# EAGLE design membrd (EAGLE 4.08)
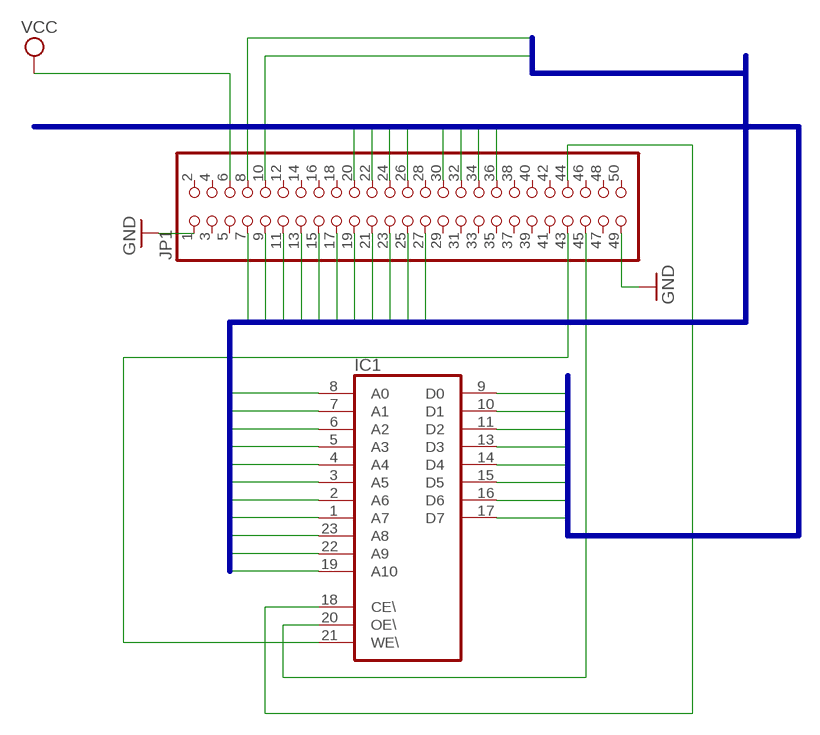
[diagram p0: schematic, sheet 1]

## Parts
IC1  2816  [DIL24]
JP1  PINHD-2X25  [2X25]

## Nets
A0: IC1.8(A0) JP1.27
A1: IC1.7(A1) JP1.25
A2: IC1.6(A2) JP1.23
A3: IC1.5(A3) JP1.21
A4: IC1.4(A4) JP1.19
A5: IC1.3(A5) JP1.17
A6: IC1.2(A6) JP1.15
A7: IC1.1(A7) JP1.13
A8: IC1.23(A8) JP1.11
A9: IC1.22(A9) JP1.9
A10: IC1.19(A10) JP1.7
A11: JP1.8
A12: JP1.10
D0: IC1.9(D0) JP1.34
D1: IC1.10(D1) JP1.36
D2: IC1.11(D2) JP1.30
D3: IC1.13(D3) JP1.22
D4: IC1.14(D4) JP1.20
D5: IC1.15(D5) JP1.24
D6: IC1.16(D6) JP1.26
D7: IC1.17(D7) JP1.32
GND: JP1.1
N$1: IC1.18(CE\) JP1.44
N$2: IC1.20(OE\) JP1.45
N$3: IC1.21(WE\) JP1.43
VCC: JP1.6
Unconnected: JP1.2 JP1.3 JP1.4 JP1.5 JP1.12 JP1.14 JP1.16 JP1.18 JP1.28 JP1.29 JP1.31 JP1.33 JP1.35 JP1.37 JP1.38 JP1.39 JP1.40 JP1.41 JP1.42 JP1.46 JP1.47 JP1.48 JP1.49 JP1.50

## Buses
D[0..7]
A[0..15]

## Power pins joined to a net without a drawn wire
GND: IC1.12(GND)
VCC: IC1.24(VCC)

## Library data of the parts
IC1 = memory:2816: MEMORY
JP1 = pinhead:PINHD-2X25: PIN HEADER

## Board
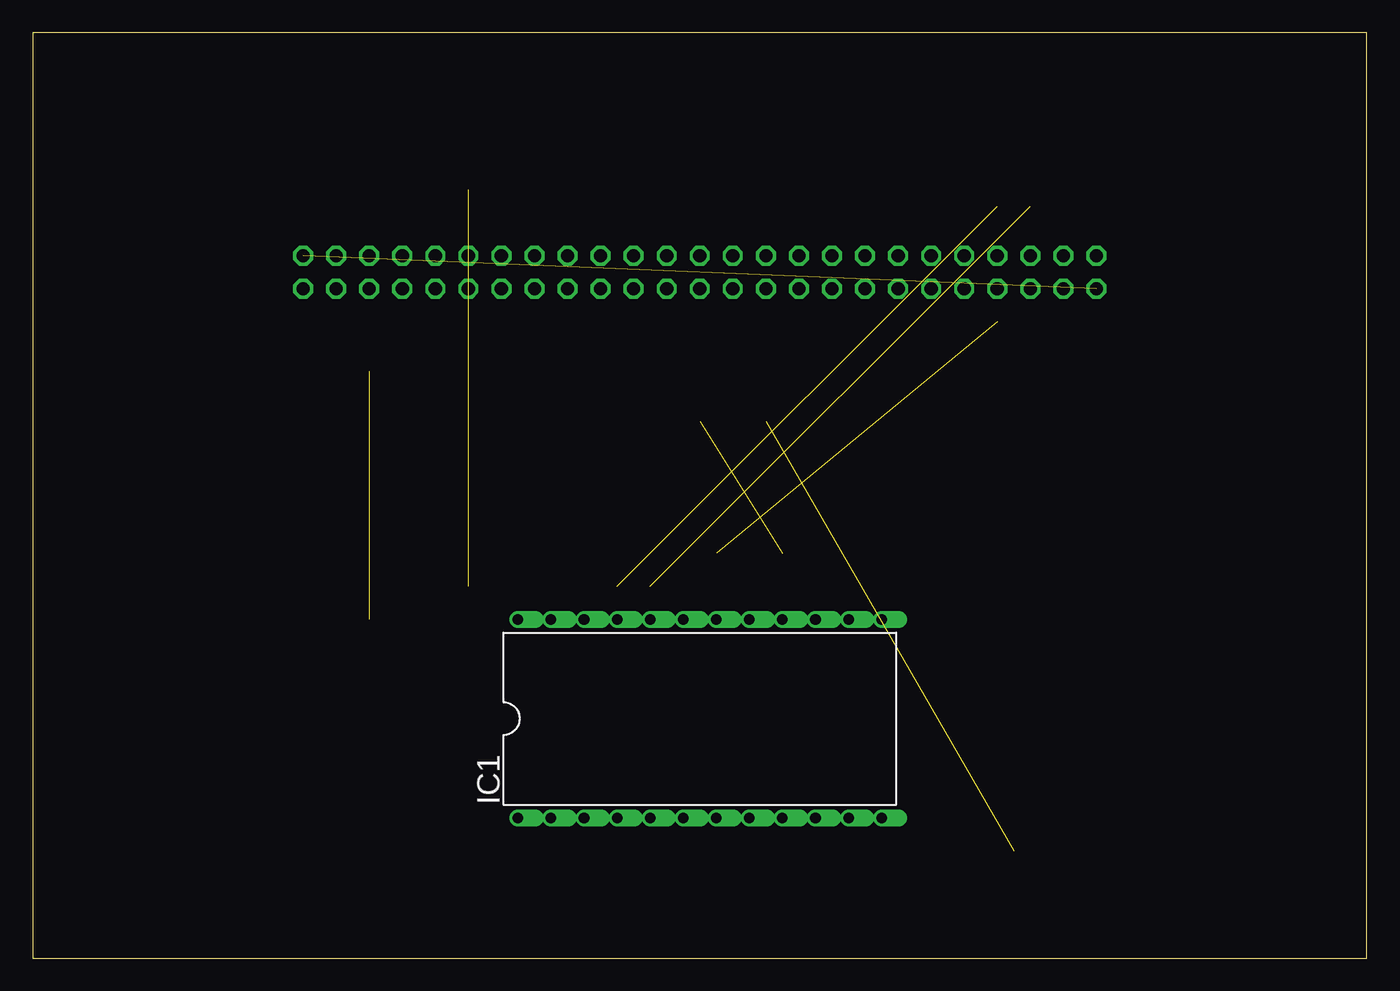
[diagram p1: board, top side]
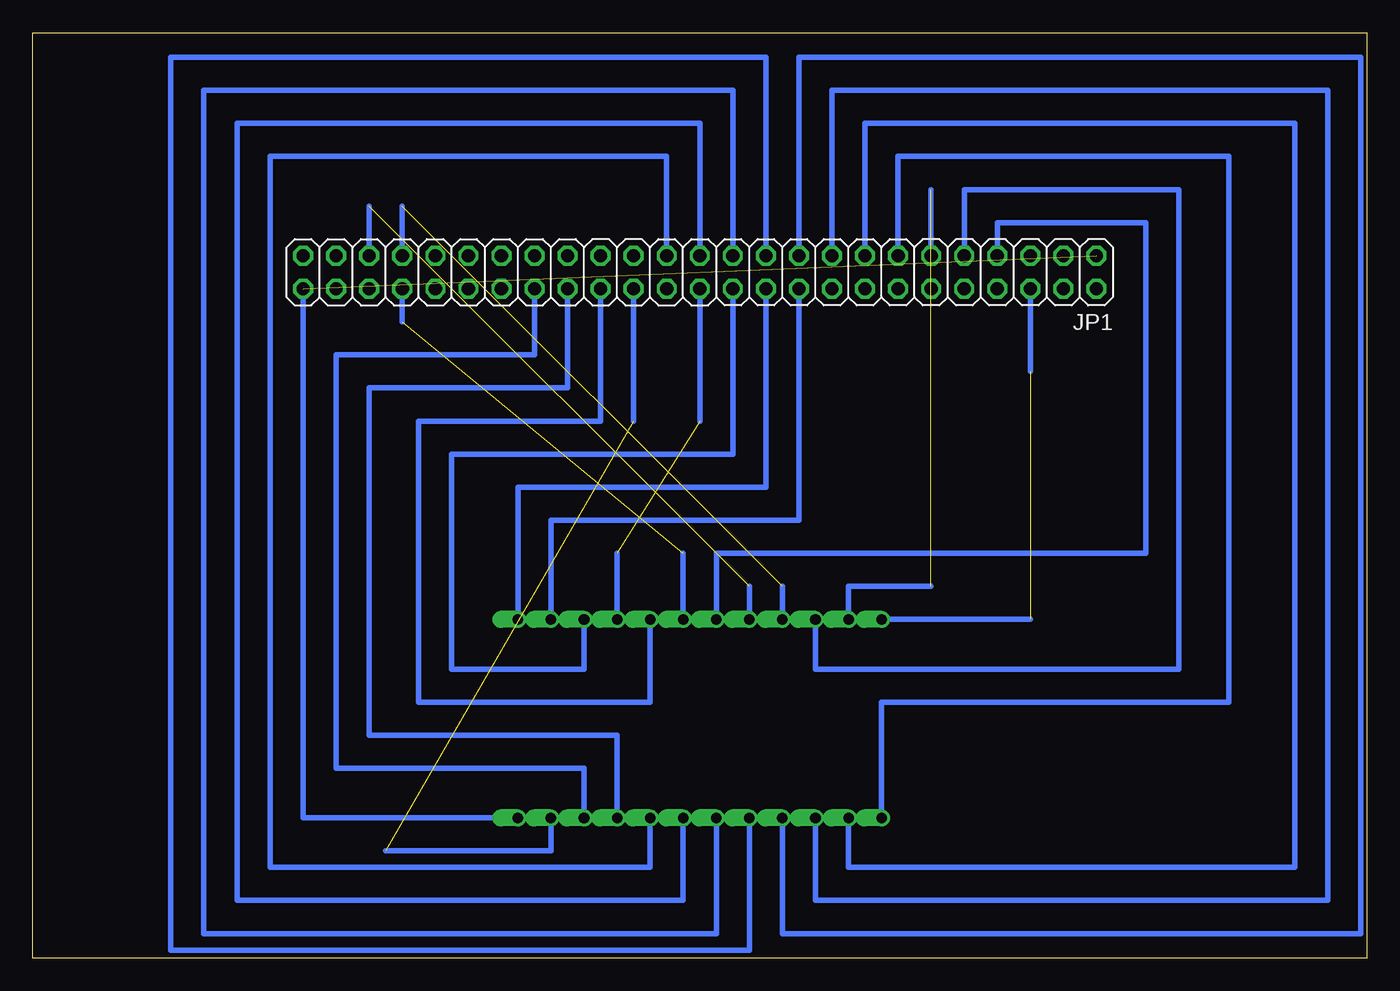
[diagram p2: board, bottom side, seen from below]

Size 102.54 x 71.11 mm. Coordinates in mm from the lower left corner, seen from the top.
Outline: 0,0 102.54,0 102.54,71.11 0,71.11 0,0
Copper layers used: Bottom

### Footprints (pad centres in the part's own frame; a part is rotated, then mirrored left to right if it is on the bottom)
DIL24 = drill 0.813 offset: 1 -13.97,-7.62; 2 -11.43,-7.62; 3 -8.89,-7.62; 4 -6.35,-7.62; 5 -3.81,-7.62; 6 -1.27,-7.62; 7 1.27,-7.62; 8 3.81,-7.62; 9 6.35,-7.62; 10 8.89,-7.62; 11 11.43,-7.62; 12 13.97,-7.62; 13 13.97,7.62; 14 11.43,7.62; 15 8.89,7.62; 16 6.35,7.62; 17 3.81,7.62; 18 1.27,7.62; 19 -1.27,7.62; 20 -3.81,7.62; 21 -6.35,7.62; 22 -8.89,7.62; 23 -11.43,7.62; 24 -13.97,7.62
2X25 = drill 1.016 octagon: 1 -30.48,-1.27; 2 -30.48,1.27; 3 -27.94,-1.27; 4 -27.94,1.27; 5 -25.4,-1.27; 6 -25.4,1.27; 7 -22.86,-1.27; 8 -22.86,1.27; 9 -20.32,-1.27; 10 -20.32,1.27; 11 -17.78,-1.27; 12 -17.78,1.27; 13 -15.24,-1.27; 14 -15.24,1.27; 15 -12.7,-1.27; 16 -12.7,1.27; 17 -10.16,-1.27; 18 -10.16,1.27; 19 -7.62,-1.27; 20 -7.62,1.27; 21 -5.08,-1.27; 22 -5.08,1.27; 23 -2.54,-1.27; 24 -2.54,1.27; 25 0,-1.27; 26 0,1.27; 27 2.54,-1.27; 28 2.54,1.27; 29 5.08,-1.27; 30 5.08,1.27; 31 7.62,-1.27; 32 7.62,1.27; 33 10.16,-1.27; 34 10.16,1.27; 35 12.7,-1.27; 36 12.7,1.27; 37 15.24,-1.27; 38 15.24,1.27; 39 17.78,-1.27; 40 17.78,1.27; 41 20.32,-1.27; 42 20.32,1.27; 43 22.86,-1.27; 44 22.86,1.27; 45 25.4,-1.27; 46 25.4,1.27; 47 27.94,-1.27; 48 27.94,1.27; 49 30.48,-1.27; 50 30.48,1.27

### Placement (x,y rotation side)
IC1  51.27,18.41 0 top
JP1  51.27,52.7 180 bottom

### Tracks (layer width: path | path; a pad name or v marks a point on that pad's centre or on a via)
A0
  Bottom 0.406: JP1.27 53.81,61.59 84.29,61.59 84.29,6.98 55.08,6.98 IC1.8
A1
  Bottom 0.406: JP1.25 51.27,64.13 86.83,64.13 86.83,4.44 52.54,4.44 IC1.7
A2
  Bottom 0.406: JP1.23 48.73,66.67 89.37,66.67 89.37,1.9 50,1.9 IC1.6
A3
  Bottom 0.406: JP1.21 46.19,69.21 91.91,69.21 91.91,0.63 47.46,0.63 IC1.5
A4
  Bottom 0.406: IC1.4 44.92,1.9 0.47,1.9 0.47,69.21 43.65,69.21 JP1.19
A5
  Bottom 0.406: JP1.17 41.11,66.67 3.01,66.67 3.01,4.44 42.38,4.44 IC1.3
A6
  Bottom 0.406: JP1.15 38.57,64.13 5.55,64.13 5.55,6.98 39.84,6.98 IC1.2
A7
  Bottom 0.406: JP1.13 36.03,61.59 10.63,61.59 10.63,19.68 37.3,19.68 IC1.1
A8  (1 unrouted)
  Bottom 0.406: JP1.11 33.49,59.05 | IC1.23 39.84,28.57 33.49,28.57
A9
  Bottom 0.406: JP1.9 30.95,59.05 14.44,59.05 14.44,22.22 42.38,22.22 IC1.22
A10
  Bottom 0.406: JP1.7 28.41,56.51 16.98,56.51 16.98,31.11 50,31.11 IC1.19
D0
  Bottom 0.406: IC1.9 57.62,17.14 76.67,17.14 76.67,43.81 61.43,43.81 JP1.34
D1
  Bottom 0.406: IC1.10 60.16,14.6 79.21,14.6 79.21,46.35 63.97,46.35 JP1.36
D2  (1 unrouted)
  Bottom 0.406: IC1.11 62.7,8.25 75.4,8.25 | JP1.30 56.35,41.27
D3
  Bottom 0.406: JP1.22 46.19,36.19 65.24,36.19 IC1.13
D4
  Bottom 0.406: JP1.20 43.65,33.65 62.7,33.65 IC1.14
D5
  Bottom 0.406: JP1.24 48.73,38.73 70.32,38.73 70.32,22.22 60.16,22.22 IC1.15
D6  (1 unrouted)
  Bottom 0.406: IC1.16 57.62,31.11 | JP1.26 51.27,41.27
D7
  Bottom 0.406: IC1.17 55.08,19.68 72.86,19.68 72.86,41.27 58.89,41.27 JP1.32
GND  (1 unrouted)
  Bottom 0.406: IC1.12 81.75,10.79 81.75,51.43
N$1  (1 unrouted)
  Bottom 0.406: IC1.18 52.54,31.11 | JP1.44 74.13,48.89
N$2  (1 unrouted)
  Bottom 0.406: JP1.45 76.67,57.78 | IC1.20 47.46,28.57
N$3  (1 unrouted)
  Bottom 0.406: JP1.43 74.13,57.78 | IC1.21 44.92,28.57
VCC  (1 unrouted)
  Bottom 0.406: IC1.24 25.87,26.03 | JP1.6 25.87,45.08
